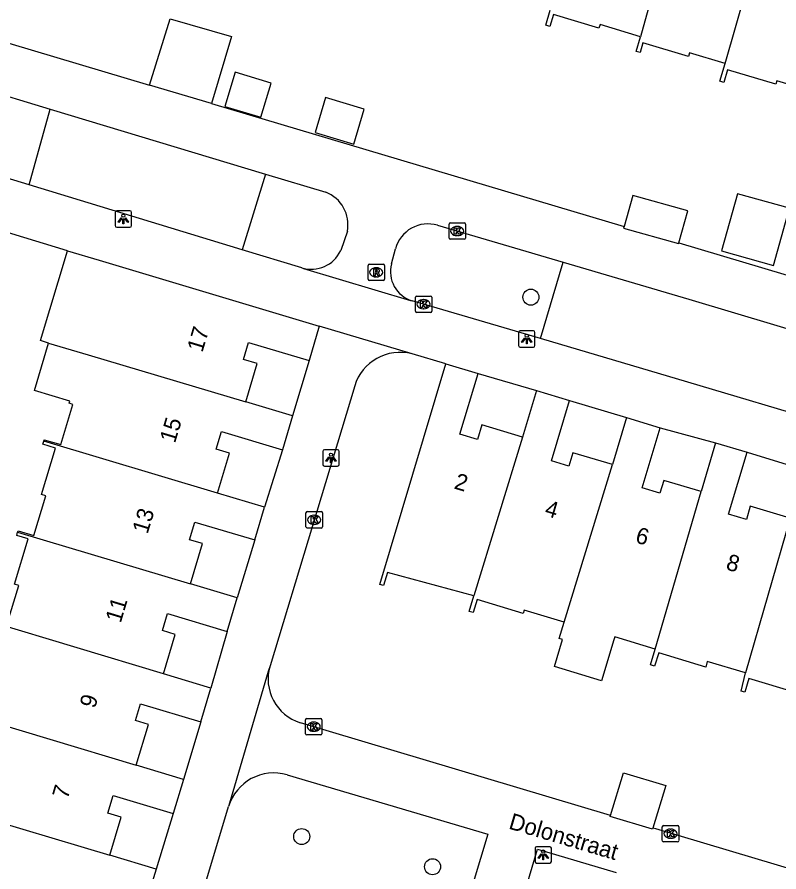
# Model space of a CAD drawing. Extents: x 162186 to 163152, y 385513 to 386513.
# Drawn here: x 162610.2 to 162656.7, y 386181.2 to 386233.4 of the extents above; entities that cross this region are included whole.
import ezdxf

# ---------------------------------------------------------------- set-up
doc = ezdxf.new("R2010")
doc.units = 0
for name, color, linetype in [('IMGEO_Boom', 7, 'Continuous'), ('IMGEO_Groenvoorziening', 7, 'Continuous'), ('IMGEO_Kolk', 7, 'Continuous'), ('IMGEO_Lichtpunt', 7, 'Continuous'), ('IMGEO_Openbare_ruimte_label', 7, 'Continuous'), ('IMGEO_Pand', 7, 'Continuous'), ('IMGEO_Pand_nummerreeks', 7, 'Continuous'), ('IMGEO_Rioolput', 7, 'Continuous'), ('IMGEO_Voetpad_open', 7, 'Continuous')]:
    doc.layers.add(name, color=color, linetype=linetype)

msp = doc.modelspace()

# ---------------------------------------------------------------- linework, layer by layer
at = {"layer": 'IMGEO_Boom'}
for centre in [(162641.558, 386216.282), (162627.561, 386183.352), (162635.553, 386181.509)]:
    msp.add_circle(centre, 0.489, dxfattribs=at)
at = {"layer": 'IMGEO_Groenvoorziening'}
for points in [[(162610.908, 386223.133), (162612.203, 386227.76)], [(162625.355, 386223.79), (162623.924, 386219.178)], [(162642.14, 386213.753), (162643.529, 386218.419)]]:
    msp.add_lwpolyline(points, dxfattribs=at)
at = {"layer": 'IMGEO_Kolk'}
for p, q in [((162636.559, 386219.893), (162636.559, 386220.745)), ((162636.634, 386220.819), (162637.486, 386220.819)), ((162637.047, 386220.599), (162637.072, 386220.599)), ((162637.56, 386220.745), (162637.56, 386219.893)), ((162637.07, 386220.039), (162637.045, 386220.039)), ((162637.486, 386219.819), (162636.634, 386219.819)), ((162634.502, 386215.427), (162634.502, 386216.279)), ((162634.577, 386216.353), (162635.429, 386216.353)), ((162635.503, 386216.279), (162635.503, 386215.427)), ((162634.99, 386216.133), (162635.015, 386216.133)), ((162635.429, 386215.353), (162634.577, 386215.353)), ((162635.013, 386215.573), (162634.988, 386215.573)), ((162627.897, 386203.188), (162628.749, 386203.188)), ((162627.822, 386202.262), (162627.822, 386203.114)), ((162628.31, 386202.968), (162628.335, 386202.968)), ((162628.823, 386203.114), (162628.823, 386202.262)), ((162628.749, 386202.188), (162627.897, 386202.188)), ((162628.333, 386202.408), (162628.308, 386202.408)), ((162627.795, 386189.629), (162627.795, 386190.481)), ((162627.87, 386190.555), (162628.722, 386190.555)), ((162628.283, 386190.335), (162628.308, 386190.335)), ((162628.796, 386190.481), (162628.796, 386189.629)), ((162628.306, 386189.775), (162628.281, 386189.775)), ((162628.722, 386189.555), (162627.87, 386189.555)), ((162649.588, 386183.099), (162649.588, 386183.951)), ((162649.663, 386184.025), (162650.515, 386184.025)), ((162650.589, 386183.951), (162650.589, 386183.099)), ((162650.076, 386183.805), (162650.101, 386183.805)), ((162650.515, 386183.025), (162649.663, 386183.025)), ((162650.099, 386183.245), (162650.074, 386183.245))]:
    msp.add_line(p, q, dxfattribs=at)
for points in [[(162636.559, 386219.893), (162636.559, 386220.745)], [(162636.634, 386220.819), (162637.486, 386220.819)], [(162636.88, 386220.519), (162637.003, 386220.519), (162637.003, 386220.368), (162637.133, 386220.519), (162637.297, 386220.519), (162637.151, 386220.368), (162637.304, 386220.119), (162637.152, 386220.119), (162637.067, 386220.283), (162637.003, 386220.216), (162637.003, 386220.119), (162636.88, 386220.119), (162636.88, 386220.519)], [(162637.56, 386220.745), (162637.56, 386219.893)], [(162637.486, 386219.819), (162636.634, 386219.819)], [(162634.502, 386215.427), (162634.502, 386216.279)], [(162634.577, 386216.353), (162635.429, 386216.353)], [(162635.503, 386216.279), (162635.503, 386215.427)], [(162634.823, 386216.053), (162634.946, 386216.053), (162634.946, 386215.902), (162635.076, 386216.053), (162635.24, 386216.053), (162635.094, 386215.902), (162635.247, 386215.653), (162635.095, 386215.653), (162635.01, 386215.817), (162634.946, 386215.75), (162634.946, 386215.653), (162634.823, 386215.653), (162634.823, 386216.053)], [(162635.429, 386215.353), (162634.577, 386215.353)], [(162627.897, 386203.188), (162628.749, 386203.188)], [(162627.822, 386202.262), (162627.822, 386203.114)], [(162628.143, 386202.888), (162628.266, 386202.888), (162628.266, 386202.737), (162628.396, 386202.888), (162628.56, 386202.888), (162628.414, 386202.737), (162628.567, 386202.488), (162628.415, 386202.488), (162628.33, 386202.652), (162628.266, 386202.585), (162628.266, 386202.488), (162628.143, 386202.488), (162628.143, 386202.888)], [(162628.823, 386203.114), (162628.823, 386202.262)], [(162628.749, 386202.188), (162627.897, 386202.188)], [(162627.795, 386189.629), (162627.795, 386190.481)], [(162627.87, 386190.555), (162628.722, 386190.555)], [(162628.116, 386190.255), (162628.239, 386190.255), (162628.239, 386190.104), (162628.369, 386190.255), (162628.533, 386190.255), (162628.387, 386190.104), (162628.54, 386189.855), (162628.388, 386189.855), (162628.303, 386190.019), (162628.239, 386189.952), (162628.239, 386189.855), (162628.116, 386189.855), (162628.116, 386190.255)], [(162628.796, 386190.481), (162628.796, 386189.629)], [(162628.722, 386189.555), (162627.87, 386189.555)], [(162649.588, 386183.099), (162649.588, 386183.951)], [(162649.663, 386184.025), (162650.515, 386184.025)], [(162650.589, 386183.951), (162650.589, 386183.099)], [(162649.909, 386183.725), (162650.032, 386183.725), (162650.032, 386183.574), (162650.162, 386183.725), (162650.326, 386183.725), (162650.18, 386183.574), (162650.333, 386183.325), (162650.181, 386183.325), (162650.096, 386183.489), (162650.032, 386183.422), (162650.032, 386183.325), (162649.909, 386183.325), (162649.909, 386183.725)], [(162650.515, 386183.025), (162649.663, 386183.025)]]:
    msp.add_lwpolyline(points, dxfattribs=at)
for centre, start, end in [((162636.636, 386220.743), 91.552, 178.448), ((162636.636, 386220.743), 91.552, 178.448), ((162637.484, 386220.743), 1.552, 88.448), ((162637.484, 386220.743), 1.552, 88.448), ((162636.636, 386219.895), 181.552, 268.448), ((162636.636, 386219.895), 181.552, 268.448), ((162637.484, 386219.895), 271.552, 358.448), ((162637.484, 386219.895), 271.552, 358.448), ((162634.579, 386216.277), 91.552, 178.448), ((162634.579, 386216.277), 91.552, 178.448), ((162635.427, 386216.277), 1.552, 88.448), ((162635.427, 386216.277), 1.552, 88.448), ((162634.579, 386215.429), 181.552, 268.448), ((162634.579, 386215.429), 181.552, 268.448), ((162635.427, 386215.429), 271.552, 358.448), ((162635.427, 386215.429), 271.552, 358.448), ((162627.899, 386203.112), 91.552, 178.448), ((162627.899, 386203.112), 91.552, 178.448), ((162628.747, 386203.112), 1.552, 88.448), ((162628.747, 386203.112), 1.552, 88.448), ((162627.899, 386202.264), 181.552, 268.448), ((162627.899, 386202.264), 181.552, 268.448), ((162628.747, 386202.264), 271.552, 358.448), ((162628.747, 386202.264), 271.552, 358.448), ((162627.872, 386190.479), 91.552, 178.448), ((162627.872, 386190.479), 91.552, 178.448), ((162628.72, 386190.479), 1.552, 88.448), ((162628.72, 386190.479), 1.552, 88.448), ((162627.872, 386189.631), 181.552, 268.448), ((162627.872, 386189.631), 181.552, 268.448), ((162628.72, 386189.631), 271.552, 358.448), ((162628.72, 386189.631), 271.552, 358.448), ((162649.665, 386183.949), 91.552, 178.448), ((162649.665, 386183.949), 91.552, 178.448), ((162650.513, 386183.949), 1.552, 88.448), ((162650.513, 386183.949), 1.552, 88.448), ((162649.665, 386183.101), 181.552, 268.448), ((162649.665, 386183.101), 181.552, 268.448), ((162650.513, 386183.101), 271.552, 358.448), ((162650.513, 386183.101), 271.552, 358.448)]:
    msp.add_arc(centre, 0.0765, start, end, dxfattribs=at)
for centre, major_axis, ratio, start_param, end_param in [((162637.046, 386220.319), (-0.387, 0.002), 0.722429, 4.712389, 7.853982), ((162637.071, 386220.319), (-0.39, 0.002), 0.717154, 1.570796, 4.712389), ((162634.989, 386215.853), (-0.387, 0.002), 0.722429, 4.712389, 7.853982), ((162635.014, 386215.853), (-0.39, 0.002), 0.717154, 1.570796, 4.712389), ((162628.309, 386202.688), (-0.387, 0.002), 0.722429, 4.712389, 7.853982), ((162628.334, 386202.688), (-0.39, 0.002), 0.717154, 1.570796, 4.712389), ((162628.282, 386190.055), (-0.387, 0.002), 0.722429, 4.712389, 7.853982), ((162628.307, 386190.055), (-0.39, 0.002), 0.717154, 1.570796, 4.712389), ((162650.075, 386183.525), (-0.387, 0.002), 0.722429, 4.712389, 7.853982), ((162650.1, 386183.525), (-0.39, 0.002), 0.717154, 1.570796, 4.712389)]:
    msp.add_ellipse(centre, major_axis=major_axis, ratio=ratio, start_param=start_param, end_param=end_param, dxfattribs=at)
at = {"layer": 'IMGEO_Lichtpunt'}
for p, q in [((162616.166, 386221.459), (162616.166, 386220.652)), ((162616.166, 386221.459), (162616.166, 386220.652)), ((162617.068, 386221.554), (162616.26, 386221.554)), ((162617.068, 386221.554), (162616.26, 386221.554)), ((162617.162, 386220.652), (162617.162, 386221.459)), ((162617.162, 386220.652), (162617.162, 386221.459)), ((162616.26, 386220.558), (162617.068, 386220.558)), ((162616.26, 386220.558), (162617.068, 386220.558)), ((162640.808, 386214.134), (162640.808, 386213.327)), ((162640.808, 386214.134), (162640.808, 386213.327)), ((162641.71, 386214.229), (162640.902, 386214.229)), ((162641.71, 386214.229), (162640.902, 386214.229)), ((162641.804, 386213.327), (162641.804, 386214.134)), ((162641.804, 386213.327), (162641.804, 386214.134)), ((162640.902, 386213.233), (162641.71, 386213.233)), ((162640.902, 386213.233), (162641.71, 386213.233)), ((162628.851, 386206.869), (162628.851, 386206.062)), ((162628.851, 386206.869), (162628.851, 386206.062)), ((162629.753, 386206.964), (162628.945, 386206.964)), ((162629.753, 386206.964), (162628.945, 386206.964)), ((162629.847, 386206.062), (162629.847, 386206.869)), ((162629.847, 386206.062), (162629.847, 386206.869)), ((162628.945, 386205.968), (162629.753, 386205.968)), ((162628.945, 386205.968), (162629.753, 386205.968)), ((162641.815, 386182.633), (162641.815, 386181.826)), ((162641.815, 386182.633), (162641.815, 386181.826)), ((162642.717, 386182.728), (162641.909, 386182.728)), ((162642.717, 386182.728), (162641.909, 386182.728)), ((162642.811, 386181.826), (162642.811, 386182.633)), ((162642.811, 386181.826), (162642.811, 386182.633)), ((162641.909, 386181.732), (162642.717, 386181.732)), ((162641.909, 386181.732), (162642.717, 386181.732))]:
    msp.add_line(p, q, dxfattribs=at)
for points in [[(162616.54, 386221.123), (162616.579, 386221.095), (162616.391, 386220.833), (162616.353, 386220.86), (162616.54, 386221.123)], [(162616.642, 386221.075), (162616.689, 386221.075), (162616.689, 386220.753), (162616.642, 386220.753), (162616.642, 386221.075)], [(162616.752, 386221.095), (162616.79, 386221.122), (162616.977, 386220.86), (162616.938, 386220.832), (162616.752, 386221.095)], [(162641.182, 386213.798), (162641.221, 386213.77), (162641.033, 386213.508), (162640.995, 386213.535), (162641.182, 386213.798)], [(162641.284, 386213.75), (162641.331, 386213.75), (162641.331, 386213.428), (162641.284, 386213.428), (162641.284, 386213.75)], [(162641.394, 386213.77), (162641.432, 386213.797), (162641.619, 386213.535), (162641.58, 386213.507), (162641.394, 386213.77)], [(162629.225, 386206.533), (162629.264, 386206.505), (162629.076, 386206.243), (162629.038, 386206.27), (162629.225, 386206.533)], [(162629.327, 386206.485), (162629.374, 386206.485), (162629.374, 386206.163), (162629.327, 386206.163), (162629.327, 386206.485)], [(162629.437, 386206.505), (162629.475, 386206.532), (162629.662, 386206.27), (162629.623, 386206.242), (162629.437, 386206.505)], [(162642.189, 386182.297), (162642.228, 386182.269), (162642.04, 386182.007), (162642.002, 386182.034), (162642.189, 386182.297)], [(162642.401, 386182.269), (162642.439, 386182.296), (162642.626, 386182.034), (162642.587, 386182.006), (162642.401, 386182.269)], [(162642.291, 386182.249), (162642.338, 386182.249), (162642.338, 386181.927), (162642.291, 386181.927), (162642.291, 386182.249)]]:
    msp.add_lwpolyline(points, dxfattribs=at)
for centre in [(162616.665, 386221.257), (162641.307, 386213.932), (162629.35, 386206.667), (162642.314, 386182.431)]:
    msp.add_circle(centre, 0.0994, dxfattribs=at)
for centre, start, end in [((162616.26, 386221.459), 90, 180), ((162616.26, 386221.459), 90, 180), ((162617.068, 386221.459), 0, 90), ((162617.068, 386221.459), 0, 90), ((162616.26, 386220.652), 180, 270), ((162616.26, 386220.652), 180, 270), ((162617.068, 386220.652), 270, 0), ((162617.068, 386220.652), 270, 360), ((162640.902, 386214.134), 90, 180), ((162640.902, 386214.134), 90, 180), ((162641.71, 386214.134), 0, 90), ((162641.71, 386214.134), 0, 90), ((162640.902, 386213.327), 180, 270), ((162640.902, 386213.327), 180, 270), ((162641.71, 386213.327), 270, 0), ((162641.71, 386213.327), 270, 360), ((162628.945, 386206.869), 90, 180), ((162628.945, 386206.869), 90, 180), ((162629.753, 386206.869), 0, 90), ((162629.753, 386206.869), 0, 90), ((162628.945, 386206.062), 180, 270), ((162628.945, 386206.062), 180, 270), ((162629.753, 386206.062), 270, 0), ((162629.753, 386206.062), 270, 360), ((162641.909, 386182.633), 90, 180), ((162641.909, 386182.633), 90, 180), ((162642.717, 386182.633), 0, 90), ((162642.717, 386182.633), 0, 90), ((162641.909, 386181.826), 180, 270), ((162641.909, 386181.826), 180, 270), ((162642.717, 386181.826), 270, 0), ((162642.717, 386181.826), 270, 360)]:
    msp.add_arc(centre, 0.0946, start, end, dxfattribs=at)
at = {"layer": 'IMGEO_Pand'}
for points in [[(162650.864, 386241.582), (162648.254, 386232.187)], [(162653.42, 386230.552), (162656.16, 386240.073)], [(162648.254, 386232.187), (162645.785, 386232.927), (162645.72, 386232.711), (162642.939, 386233.544), (162642.721, 386232.815), (162642.466, 386232.891), (162642.737, 386233.798)], [(162618.261, 386229.221), (162619.516, 386233.282), (162623.27, 386232.189), (162622.043, 386228.107)], [(162653.42, 386230.552), (162651.252, 386231.202), (162651.187, 386230.986), (162648.406, 386231.819), (162648.226, 386231.216), (162647.985, 386231.288), (162648.254, 386232.187)], [(162658.951, 386228.771), (162656.576, 386229.482), (162656.519, 386229.292), (162653.579, 386230.172), (162653.343, 386229.386), (162653.093, 386229.461), (162653.42, 386230.552)], [(162625.067, 386227.269), (162625.693, 386229.353), (162623.5, 386230.012), (162622.873, 386227.928), (162625.067, 386227.269)], [(162622.043, 386228.107), (162618.261, 386229.221)], [(162630.743, 386225.628), (162631.383, 386227.757), (162629.023, 386228.466), (162628.383, 386226.338), (162630.743, 386225.628)], [(162650.593, 386219.592), (162651.141, 386221.554), (162647.783, 386222.491), (162647.252, 386220.589)], [(162656.387, 386218.216), (162657.362, 386221.709), (162654.172, 386222.599), (162653.198, 386219.106), (162656.387, 386218.216)], [(162647.252, 386220.589), (162647.227, 386220.499), (162650.585, 386219.562), (162650.593, 386219.592)], [(162612.103, 386213.478), (162611.606, 386213.627), (162613.252, 386219.119)], [(162613.252, 386219.119), (162615.184, 386218.54), (162628.636, 386214.511)], [(162628.636, 386214.511), (162628.008, 386212.413)], [(162611.812, 386207.493), (162611.838, 386207.58), (162612.839, 386207.28), (162613.574, 386209.736), (162613.358, 386209.801), (162613.398, 386209.934), (162611.236, 386210.581), (162612.103, 386213.478)], [(162612.103, 386213.478), (162614.519, 386212.754), (162624.147, 386209.891)], [(162624.147, 386209.891), (162624.85, 386212.236), (162624.01, 386212.487), (162624.319, 386213.517), (162628.008, 386212.413)], [(162638.083, 386198.049), (162632.799, 386199.472), (162632.562, 386198.678), (162632.335, 386198.745), (162636.361, 386212.211)], [(162636.361, 386212.211), (162638.337, 386211.62)], [(162641.043, 386207.741), (162638.564, 386208.482), (162638.297, 386207.588), (162637.227, 386207.908), (162638.337, 386211.62)], [(162641.893, 386210.584), (162641.043, 386207.741)], [(162641.893, 386210.584), (162643.925, 386209.976)], [(162646.545, 386206.061), (162644.118, 386206.786), (162643.873, 386205.968), (162642.821, 386206.283), (162643.925, 386209.976)], [(162627, 386209.037), (162624.147, 386209.891)], [(162627, 386209.037), (162626.379, 386206.962)], [(162647.403, 386208.926), (162646.545, 386206.061)], [(162647.403, 386208.926), (162649.456, 386208.312)], [(162622.427, 386204.312), (162623.159, 386206.754), (162622.336, 386207.001), (162622.658, 386208.077), (162626.379, 386206.962)], [(162651.953, 386204.424), (162649.674, 386205.093), (162649.443, 386204.32), (162648.36, 386204.644), (162649.456, 386208.312)], [(162610.21, 386201.931), (162610.236, 386202.017), (162611.208, 386201.727), (162611.934, 386204.151), (162611.676, 386204.228), (162612.528, 386207.072), (162611.755, 386207.303), (162611.812, 386207.493)], [(162622.427, 386204.312), (162611.812, 386207.493)], [(162641.043, 386207.741), (162638.083, 386198.049)], [(162652.831, 386207.384), (162651.953, 386204.424)], [(162652.831, 386207.384), (162654.763, 386206.811)], [(162657.393, 386202.799), (162654.964, 386203.52), (162654.722, 386202.706), (162653.64, 386203.027), (162654.763, 386206.811)], [(162643.592, 386196.442), (162646.545, 386206.061)], [(162625.29, 386203.455), (162622.427, 386204.312)], [(162649.16, 386194.793), (162651.953, 386204.424)], [(162624.692, 386201.458), (162625.29, 386203.455)], [(162657.393, 386202.799), (162654.673, 386193.336)], [(162620.773, 386198.781), (162621.509, 386201.237), (162620.711, 386201.476), (162621.034, 386202.553), (162624.692, 386201.458)], [(162608.544, 386196.455), (162608.558, 386196.503), (162609.538, 386196.211), (162610.277, 386198.677), (162610.024, 386198.753), (162610.856, 386201.53), (162610.153, 386201.74), (162610.21, 386201.931)], [(162610.21, 386201.931), (162620.773, 386198.781)], [(162623.623, 386197.928), (162620.773, 386198.781)], [(162643.592, 386196.442), (162641.157, 386197.17), (162641.097, 386196.97), (162638.271, 386197.815), (162638.036, 386197.029), (162637.799, 386197.1), (162638.083, 386198.049)], [(162623.007, 386195.869), (162623.623, 386197.928)], [(162619.112, 386193.279), (162619.835, 386195.693), (162619.054, 386195.927), (162619.364, 386196.96), (162623.007, 386195.869)], [(162619.112, 386193.279), (162608.544, 386196.455)], [(162649.16, 386194.793), (162646.678, 386195.535), (162646.623, 386195.353), (162645.876, 386192.863), (162643.001, 386193.726), (162643.499, 386195.386), (162643.294, 386195.447), (162643.592, 386196.442)], [(162654.673, 386193.336), (162652.338, 386194.029), (162652.251, 386193.692), (162649.366, 386194.566), (162649.12, 386193.751), (162648.871, 386193.826), (162649.16, 386194.793)], [(162622.007, 386192.411), (162619.112, 386193.279)], [(162660.191, 386191.658), (162657.841, 386192.355), (162657.775, 386192.133), (162654.866, 386192.996), (162654.628, 386192.159), (162654.409, 386192.224), (162654.673, 386193.336)], [(162621.389, 386190.347), (162622.007, 386192.411)], [(162617.453, 386187.706), (162618.199, 386190.196), (162617.408, 386190.433), (162617.712, 386191.448), (162621.389, 386190.347)], [(162606.879, 386190.876), (162617.453, 386187.706)], [(162620.341, 386186.841), (162617.453, 386187.706)], [(162646.428, 386184.643), (162647.218, 386187.249), (162649.798, 386186.467), (162649.012, 386183.871)], [(162620.341, 386186.841), (162619.718, 386184.761)], [(162615.831, 386182.217), (162616.525, 386184.537), (162615.723, 386184.778), (162616.047, 386185.86), (162619.718, 386184.761)], [(162605.194, 386185.379), (162615.831, 386182.217)], [(162649.012, 386183.871), (162648.988, 386183.793), (162646.407, 386184.574), (162646.428, 386184.643)], [(162618.668, 386181.368), (162615.831, 386182.217)], [(162618.668, 386181.368), (162618.049, 386179.3)]]:
    msp.add_lwpolyline(points, dxfattribs=at)
at = {"layer": 'IMGEO_Rioolput'}
for p, q in [((162631.611, 386217.372), (162631.611, 386218.224)), ((162631.686, 386218.298), (162632.538, 386218.298)), ((162632.099, 386218.078), (162632.124, 386218.078)), ((162632.612, 386218.224), (162632.612, 386217.372)), ((162632.538, 386217.298), (162631.686, 386217.298)), ((162632.122, 386217.518), (162632.097, 386217.518))]:
    msp.add_line(p, q, dxfattribs=at)
for points in [[(162631.611, 386217.372), (162631.611, 386218.224)], [(162631.686, 386218.298), (162632.538, 386218.298)], [(162632.2, 386217.996), (162631.948, 386217.998), (162631.948, 386217.598)], [(162632.126, 386217.917), (162632.072, 386217.917), (162632.072, 386217.836)], [(162632.072, 386217.836), (162632.124, 386217.836)], [(162632.612, 386218.224), (162632.612, 386217.372)], [(162632.538, 386217.298), (162631.686, 386217.298)], [(162631.948, 386217.598), (162632.072, 386217.598), (162632.072, 386217.76), (162632.083, 386217.76)], [(162632.13, 386217.731), (162632.201, 386217.598), (162632.341, 386217.598), (162632.276, 386217.724)]]:
    msp.add_lwpolyline(points, dxfattribs=at)
for centre, radius, start, end in [((162631.688, 386218.222), 0.0765, 91.552, 178.448), ((162631.688, 386218.222), 0.0765, 91.552, 178.448), ((162632.108, 386218.025), 0.19, 274.7715, 282.9687), ((162632.132, 386217.821), 0.0964, 77.0061, 93.1865), ((162632.146, 386217.878), 0.0378, 276.6634, 79.6772), ((162632.199, 386217.886), 0.109, 350.3612, 89.416), ((162632.197, 386217.886), 0.112, 277.5842, 350.9817), ((162632.536, 386218.222), 0.0765, 1.552, 88.448), ((162632.536, 386218.222), 0.0765, 1.552, 88.448), ((162631.688, 386217.374), 0.0765, 181.552, 268.448), ((162631.688, 386217.374), 0.0765, 181.552, 268.448), ((162632.082, 386217.707), 0.0533, 26.0293, 88.6989), ((162632.181, 386217.671), 0.108, 29.5134, 73.7905), ((162632.536, 386217.374), 0.0765, 271.552, 358.448), ((162632.536, 386217.374), 0.0765, 271.552, 358.448)]:
    msp.add_arc(centre, radius, start, end, dxfattribs=at)
for centre, major_axis, ratio, start_param, end_param in [((162632.098, 386217.798), (-0.387, 0.002), 0.722429, 4.712389, 7.853982), ((162632.123, 386217.798), (-0.39, 0.002), 0.717154, 1.570796, 4.712389)]:
    msp.add_ellipse(centre, major_axis=major_axis, ratio=ratio, start_param=start_param, end_param=end_param, dxfattribs=at)
at = {"layer": 'IMGEO_Voetpad_open'}
for points in [[(162609.673, 386231.789), (162618.261, 386229.221)], [(162607.767, 386229.099), (162612.203, 386227.76)], [(162612.203, 386227.76), (162625.355, 386223.79)], [(162622.043, 386228.107), (162647.252, 386220.589)], [(162610.908, 386223.133), (162606.279, 386224.539)], [(162625.355, 386223.79), (162629.025, 386222.685)], [(162623.924, 386219.178), (162610.908, 386223.133)], [(162613.252, 386219.119), (162606.428, 386221.182)], [(162635.853, 386220.672), (162643.529, 386218.419)], [(162630.348, 386220.311), (162629.941, 386219.127)], [(162650.593, 386219.592), (162667.509, 386214.547)], [(162627.562, 386218.073), (162623.924, 386219.178)], [(162633.044, 386218.324), (162633.29, 386219.237)], [(162643.529, 386218.419), (162651.203, 386216.166), (162669.521, 386210.679)], [(162627.562, 386218.073), (162627.667, 386218.035), (162634.203, 386216.083), (162634.311, 386216.059)], [(162642.14, 386213.753), (162634.311, 386216.059)], [(162634.301, 386212.814), (162628.636, 386214.511)], [(162668.123, 386206.04), (162651.146, 386211.101), (162642.14, 386213.753)], [(162636.361, 386212.211), (162634.301, 386212.814)], [(162628.008, 386212.413), (162627, 386209.037)], [(162638.337, 386211.62), (162641.893, 386210.584)], [(162630.797, 386210.86), (162625.627, 386193.774)], [(162643.925, 386209.976), (162647.403, 386208.926)], [(162649.456, 386208.312), (162652.831, 386207.384)], [(162626.379, 386206.962), (162625.29, 386203.455)], [(162654.763, 386206.811), (162658.264, 386205.736)], [(162624.692, 386201.458), (162623.623, 386197.928)], [(162623.007, 386195.869), (162622.007, 386192.411)], [(162625.627, 386193.774), (162625.509, 386193.419), (162623.14, 386185.385), (162623.092, 386185.178)], [(162621.389, 386190.347), (162620.341, 386186.841)], [(162646.428, 386184.643), (162627.488, 386190.299)], [(162626.674, 386187.116), (162638.93, 386183.488), (162637.202, 386177.754)], [(162616.641, 386163.652), (162623.092, 386185.178)], [(162619.718, 386184.761), (162618.668, 386181.368)], [(162699.756, 386171.624), (162699.657, 386171.381), (162699.537, 386171.147), (162699.396, 386170.925), (162699.236, 386170.717), (162699.058, 386170.524), (162698.864, 386170.347), (162698.654, 386170.188), (162698.431, 386170.049), (162698.197, 386169.931), (162697.953, 386169.833), (162697.701, 386169.758), (162697.444, 386169.706), (162697.183, 386169.677), (162696.92, 386169.671), (162696.658, 386169.689), (162696.399, 386169.73), (162696.144, 386169.794), (162666.99, 386178.501), (162649.189, 386183.818), (162649.012, 386183.871)], [(162640.282, 386176.891), (162641.972, 386182.589), (162646.772, 386181.157)]]:
    msp.add_lwpolyline(points, dxfattribs=at)
for centre, radius, start, end in [((162628.287, 386220.718), 2.101, 348.8242, 69.4366), ((162635.271, 386218.705), 2.051, 73.5107, 164.9774), ((162628.14, 386219.98), 1.993, 253.137, 334.6538), ((162634.837, 386217.84), 1.857, 164.9037, 253.54), ((162633.56, 386210.024), 2.887, 75.1335, 163.1588), ((162628.295, 386192.967), 2.788, 163.1776, 253.164), ((162625.856, 386184.349), 2.885, 73.5249, 163.3052)]:
    msp.add_arc(centre, radius, start, end, dxfattribs=at)

# ---------------------------------------------------------------- texts
at = {"layer": 'IMGEO_Openbare_ruimte_label'}
msp.add_text('Dolonstraat', height=1, rotation=343.5038, dxfattribs=at).set_placement((162640.15, 386183.845))
at = {"layer": 'IMGEO_Pand_nummerreeks'}
for s, rotation, p in [('17', 73.2011, (162621.49, 386212.867)), ('15', 73.2006, (162619.817, 386207.324)), ('2', 343.4539, (162636.817, 386204.609)), ('4', 343.4539, (162642.35, 386202.964)), ('13', 73.2011, (162618.143, 386201.781)), ('6', 343.4539, (162647.883, 386201.32)), ('8', 343.4539, (162653.42, 386199.675)), ('11', 73.2011, (162616.503, 386196.348)), ('9', 73.2011, (162614.929, 386191.134)), ('7', 73.2006, (162613.257, 386185.592))]:
    msp.add_text(s, height=1, rotation=rotation, dxfattribs=at).set_placement(p)

doc.saveas('drawing.dxf')
